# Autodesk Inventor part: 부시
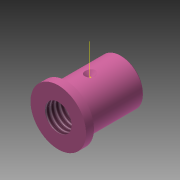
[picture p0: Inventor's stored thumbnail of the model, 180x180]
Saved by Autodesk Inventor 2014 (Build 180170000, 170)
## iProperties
Created: 2019-04
Part Number: 부시
Material: 강철, 연강
Document SubType Name: Modeling
Designer: mduedu
Density: 1 g/cm^3
Appearance: 분홍색
Author: mduedu
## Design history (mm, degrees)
sketch "스케치1"
  geometry: L1 (0, 0)-(3, 0); L2 (3, 0)-(3, 10.5); L3 (3, 10.5)-(0, 10.5); L4 (0, 10.5)-(0, 0); L5 (3, 0)-(24, 0); L6 (24, 0)-(24, 8.5); L7 (24, 8.5)-(3, 8.5); L8 (3, 8.5)-(3, 0)
  constraints: 16 end point, 4 parallel, 2 horizontal, 2 perpendicular
  dimensions: "d0" = 3 distance of L2.end L3.end; "d2" = 24 distance between parallel lines of L6 L4; "d3" = 17 diameter of L7 L5; "d4" = 21 diameter of L3 L1
revolve "회전1" sketch "스케치1" stored, may be unused: angle "d5" = 90 deg
sketch "스케치2"
  geometry: L1 (3, 8.5)-(24, 8.5) reference; L2 (12, 8.5)-(12, 6.5); L3 (12, 6.5)-(14, 8.5); L4 (0, -10.5)-(0, 10.5) reference; 1 further point
  constraints: 4 end point, 2 point on line, 1 perpendicular
  dimensions: "d6" = 12 distance from line of L2.start L4; "d7" = 2 distance of L2.start L3.end; "d8" = 45 deg angle of L3 L2
revolve "회전2" sketch "스케치2" stored, may be unused: angle "d9" = 90 deg
hole "구멍1" diameter "d12" = 10.106; stored, may be unused: countersink angle "d16" = 90 deg, drill point angle "d18" = 118 deg; dims "d10" = 10, "d11" = 10, "d13" = 39, "d14" = 4, "d15" = 2, "d17" = 8
chamfer "모따기1" distance "d19" = 0.5; stored, may be unused: second distance "d20" = 2, angle "d21" = 45 deg
node "작업점1"
  node "작업 평면1"
  node "작업축1"
node "작업점2"
  node "작업축2"
node "솔리드1"
